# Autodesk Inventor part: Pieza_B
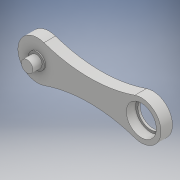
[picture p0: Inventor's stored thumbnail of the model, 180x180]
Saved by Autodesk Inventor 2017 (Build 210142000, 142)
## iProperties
Part Number: Pieza_B
Material: Genérico
Document SubType Name: Modeling
Designer: Jaime
Density: 1 g/cm^3
Appearance: Valor por defecto
Mass: 32.603 g
Surface Area: 111.922 cm^2
Volume: 32.603 cm^3
Author: Jaime
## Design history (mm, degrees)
sketch "Boceto1"
  geometry: C1 r 13 at (0, 0); C2 r 13 at (90, 0); A1 r 17 centre (90, 0) between (84.416, -16.057) and (84.416, 16.057); A2 r 17 centre (0, 0) between (5.584, 16.057) and (5.584, -16.057); A3 r 120 centre (45, 129.399) between (5.584, 16.057) and (84.416, 16.057); A4 r 120 centre (45, -129.399) between (84.416, -16.057) and (5.584, -16.057); 1 further point
  constraints: 8 point on circle, 6 centre point, 4 coincident, 4 tangent, 1 horizontal alignment
  dimensions: "d0" = 34 diameter of A1; "d1" = 34 diameter of A2; "d2" = 90 distance of A1.centre A2.centre; "d3" = 26 diameter of C1; "d4" = 26 diameter of C2; "d5" = 120 radius of A3; "d6" = 120 radius of A4
extrude "Extrusión1" new body sketch "Boceto1" distance "d7" = 10; taper "d8" = 0 deg
sketch "Boceto5"
  geometry: C1 r 11 at (0, 0); C2 r 13 at (0, 0); 1 further point
  constraints: 2 centre point, 2 coincident
  dimensions: "d18" = 22 diameter of C1; "d19" = 26 diameter of C2
extrude "Extrusión5" join sketch "Boceto5" distance "d20" = 2; taper "d21" = 0 deg
sketch "Boceto6"
  geometry: C1 r 7 at (-90, 0); A1 r 17 centre (-90, 0) between (-84.416, 16.057) and (-84.416, -16.057) reference; 1 further point
  constraints: 1 centre point, 1 concentric
  dimensions: "d23" = 14 diameter of C1
extrude "Extrusión6" join sketch "Boceto6" distance "d24" = 1; taper "d25" = 0 deg
sketch "Boceto7"
  geometry: C1 r 5 at (0, 0); C2 r 7 at (0, 0) reference; 1 further point
  constraints: 1 centre point, 1 concentric
  dimensions: "d26" = 10 diameter of C1
extrude "Extrusión7" join sketch "Boceto7" distance "d27" = 8; taper "d28" = 0 deg
node "Sólido1"
